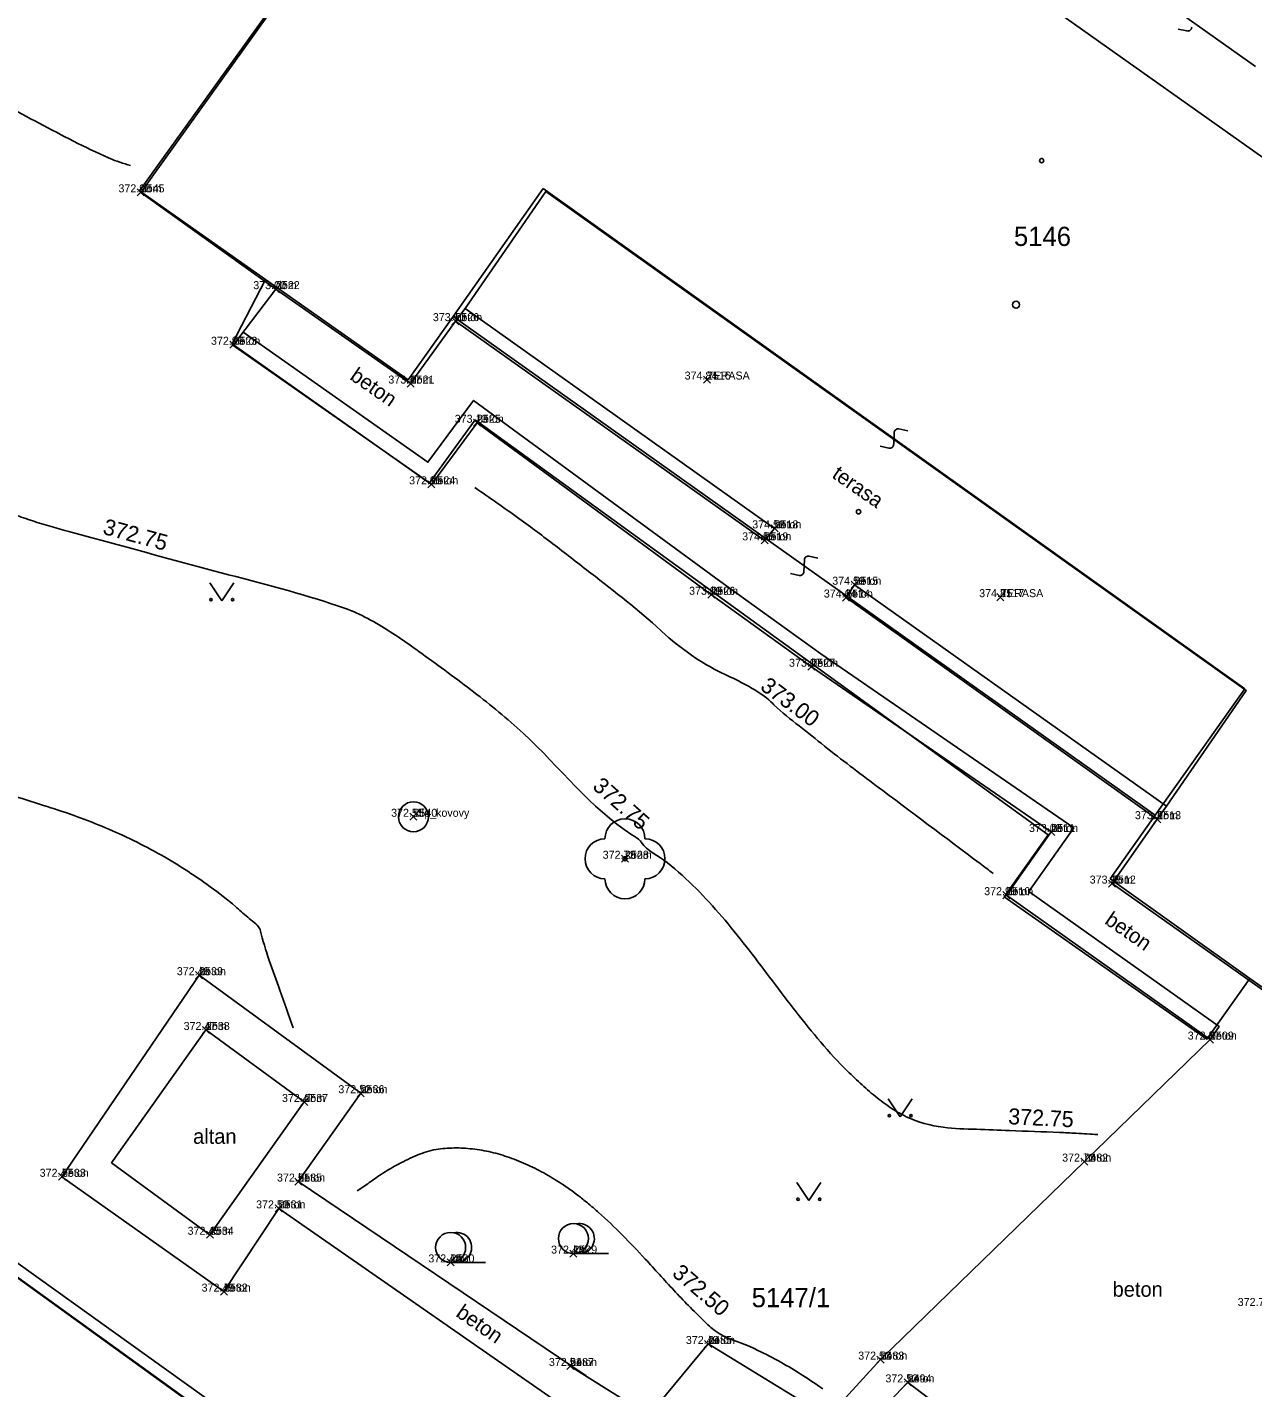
# Model space of a CAD drawing. Extents: x -400488 to -400124, y -1251493 to -1251223.
# Drawn here: x -400354.88 to -400324.23, y -1251353.83 to -1251319.82 of the extents above; entities that cross this region are included whole.
import ezdxf

# ---------------------------------------------------------------- set-up
doc = ezdxf.new("R2010")
doc.units = 0
for name, color, linetype in [('Level 20', 7, 'Continuous'), ('Level 21', 7, 'Continuous'), ('Level 22', 7, 'Continuous'), ('Level 23', 7, 'Continuous'), ('Level 31', 7, 'Continuous'), ('Level 32', 7, 'Continuous'), ('Level 34', 7, 'Continuous'), ('Level 35', 7, 'Continuous'), ('Level 36', 7, 'Continuous'), ('Level 49', 7, 'Continuous'), ('Level 60', 7, 'Continuous'), ('Level 63', 7, 'Continuous')]:
    doc.layers.add(name, color=color, linetype=linetype)

msp = doc.modelspace()

# ---------------------------------------------------------------- linework, layer by layer
at = {"layer": 'Level 20'}
for p, q in [((-400352.128, -1251324.038), (-400351.952, -1251323.862)), ((-400351.952, -1251324.038), (-400352.128, -1251323.862)), ((-400348.748, -1251326.458), (-400348.572, -1251326.282)), ((-400348.572, -1251326.458), (-400348.748, -1251326.282)), ((-400344.258, -1251327.258), (-400344.082, -1251327.082)), ((-400344.082, -1251327.258), (-400344.258, -1251327.082)), ((-400349.808, -1251327.848), (-400349.632, -1251327.672)), ((-400349.632, -1251327.848), (-400349.808, -1251327.672)), ((-400345.378, -1251328.818), (-400345.202, -1251328.642)), ((-400345.202, -1251328.818), (-400345.378, -1251328.642)), ((-400337.968, -1251328.718), (-400337.792, -1251328.542)), ((-400337.792, -1251328.718), (-400337.968, -1251328.542)), ((-400343.718, -1251329.798), (-400343.542, -1251329.622)), ((-400343.542, -1251329.798), (-400343.718, -1251329.622)), ((-400344.858, -1251331.338), (-400344.682, -1251331.162)), ((-400344.682, -1251331.338), (-400344.858, -1251331.162)), ((-400336.278, -1251332.438), (-400336.102, -1251332.262)), ((-400336.102, -1251332.438), (-400336.278, -1251332.262)), ((-400336.528, -1251332.738), (-400336.352, -1251332.562)), ((-400336.352, -1251332.738), (-400336.528, -1251332.562)), ((-400334.278, -1251333.848), (-400334.102, -1251333.672)), ((-400334.102, -1251333.848), (-400334.278, -1251333.672)), ((-400337.858, -1251334.098), (-400337.682, -1251333.922)), ((-400337.682, -1251334.098), (-400337.858, -1251333.922)), ((-400334.488, -1251334.168), (-400334.312, -1251333.992)), ((-400334.312, -1251334.168), (-400334.488, -1251333.992)), ((-400330.628, -1251334.158), (-400330.452, -1251333.982)), ((-400330.452, -1251334.158), (-400330.628, -1251333.982)), ((-400335.358, -1251335.898), (-400335.182, -1251335.722)), ((-400335.182, -1251335.898), (-400335.358, -1251335.722)), ((-400345.308, -1251339.648), (-400345.132, -1251339.472)), ((-400345.132, -1251339.648), (-400345.308, -1251339.472)), ((-400326.708, -1251339.708), (-400326.532, -1251339.532)), ((-400326.532, -1251339.708), (-400326.708, -1251339.532)), ((-400329.358, -1251340.028), (-400329.182, -1251339.852)), ((-400329.182, -1251340.028), (-400329.358, -1251339.852)), ((-400340.018, -1251340.698), (-400339.842, -1251340.522)), ((-400339.842, -1251340.698), (-400340.018, -1251340.522)), ((-400327.838, -1251341.318), (-400327.662, -1251341.142)), ((-400327.662, -1251341.318), (-400327.838, -1251341.142)), ((-400330.478, -1251341.608), (-400330.302, -1251341.432)), ((-400330.302, -1251341.608), (-400330.478, -1251341.432)), ((-400350.668, -1251343.608), (-400350.492, -1251343.432)), ((-400350.492, -1251343.608), (-400350.668, -1251343.432)), ((-400350.498, -1251344.978), (-400350.322, -1251344.802)), ((-400350.322, -1251344.978), (-400350.498, -1251344.802)), ((-400325.388, -1251345.218), (-400325.212, -1251345.042)), ((-400325.212, -1251345.218), (-400325.388, -1251345.042)), ((-400348.038, -1251346.778), (-400347.862, -1251346.602)), ((-400347.862, -1251346.778), (-400348.038, -1251346.602)), ((-400346.628, -1251346.558), (-400346.452, -1251346.382)), ((-400346.452, -1251346.558), (-400346.628, -1251346.382)), ((-400328.528, -1251348.268), (-400328.352, -1251348.092)), ((-400328.352, -1251348.268), (-400328.528, -1251348.092)), ((-400354.098, -1251348.648), (-400353.922, -1251348.472)), ((-400353.922, -1251348.648), (-400354.098, -1251348.472)), ((-400348.188, -1251348.768), (-400348.012, -1251348.592)), ((-400348.012, -1251348.768), (-400348.188, -1251348.592)), ((-400348.678, -1251349.438), (-400348.502, -1251349.262)), ((-400348.502, -1251349.438), (-400348.678, -1251349.262)), ((-400350.398, -1251350.098), (-400350.222, -1251349.922)), ((-400350.222, -1251350.098), (-400350.398, -1251349.922)), ((-400341.308, -1251350.568), (-400341.132, -1251350.392)), ((-400341.132, -1251350.568), (-400341.308, -1251350.392)), ((-400344.378, -1251350.788), (-400344.202, -1251350.612)), ((-400344.202, -1251350.788), (-400344.378, -1251350.612)), ((-400350.048, -1251351.518), (-400349.872, -1251351.342)), ((-400349.872, -1251351.518), (-400350.048, -1251351.342)), ((-400337.938, -1251352.828), (-400337.762, -1251352.652)), ((-400337.762, -1251352.828), (-400337.938, -1251352.652)), ((-400333.628, -1251353.218), (-400333.452, -1251353.042)), ((-400333.452, -1251353.218), (-400333.628, -1251353.042)), ((-400341.388, -1251353.378), (-400341.212, -1251353.202)), ((-400341.212, -1251353.378), (-400341.388, -1251353.202)), ((-400332.948, -1251353.788), (-400332.772, -1251353.612)), ((-400332.772, -1251353.788), (-400332.948, -1251353.612))]:
    msp.add_line(p, q, dxfattribs=at)
at = {"layer": 'Level 31'}
msp.add_line((-400326.388, -1251339.294), (-400334.19, -1251333.76), dxfattribs=at)
for points in [[(-400348.66, -1251326.37), (-400349.72, -1251327.76), (-400344.77, -1251331.25), (-400343.63, -1251329.71), (-400337.77, -1251334.01), (-400335.27, -1251335.81)], [(-400343.93, -1251326.85), (-400336.19, -1251332.35), (-400336.44, -1251332.65), (-400344.17, -1251327.17)], [(-400349.477, -1251327.442), (-400344.859, -1251330.698), (-400343.715, -1251329.152), (-400337.535, -1251333.686), (-400335.036, -1251335.485)], [(-400326.62, -1251339.62), (-400334.4, -1251334.08), (-400334.19, -1251333.76)], [(-400325.3, -1251345.13), (-400325.069, -1251344.804), (-400329.832, -1251341.425), (-400328.709, -1251339.84), (-400335.036, -1251335.485)], [(-400325.3, -1251345.13), (-400330.39, -1251341.52), (-400329.27, -1251339.94), (-400335.27, -1251335.81)], [(-400340.901, -1251353.538), (-400348.1, -1251348.68), (-400346.54, -1251346.47), (-400350.58, -1251343.52), (-400354.01, -1251348.56)], [(-400325.3, -1251345.13), (-400328.44, -1251348.18), (-400333.54, -1251353.13), (-400334.86, -1251354.57), (-400337.85, -1251352.74), (-400339.33, -1251354.53), (-400341.3, -1251353.29)], [(-400341.64, -1251354.18), (-400348.59, -1251349.35), (-400349.96, -1251351.43), (-400354.01, -1251348.56)], [(-400340.16, -1251356.34), (-400340.828, -1251357.382), (-400337.51, -1251359.51), (-400334.26, -1251355.13), (-400332.86, -1251353.7), (-400328.72, -1251356.82), (-400328.3, -1251357.14), (-400327.46, -1251357.74), (-400326.93, -1251358.11), (-400329.7, -1251364.82)]]:
    msp.add_lwpolyline(points, dxfattribs=at)
at = {"layer": 'Level 34'}
for points in [[(-400318.045, -1251327.281), (-400335.362, -1251315.009), (-400331.92, -1251310.33)], [(-400348.66, -1251326.37), (-400352.04, -1251323.95), (-400347.15, -1251317.14), (-400345.723, -1251318.156), (-400342.07, -1251313.16), (-400343.58, -1251312.05)], [(-400326.62, -1251339.62), (-400326.388, -1251339.294), (-400324.4, -1251336.403), (-400341.911, -1251323.928), (-400343.93, -1251326.85), (-400344.17, -1251327.17), (-400345.29, -1251328.73), (-400348.66, -1251326.37)], [(-400312.65, -1251334.13), (-400314.209, -1251333.021), (-400317.753, -1251338.016), (-400316.22, -1251339.14), (-400321.09, -1251345.94), (-400327.75, -1251341.23)], [(-400327.75, -1251341.23), (-400326.62, -1251339.62)], [(-400350.41, -1251344.89), (-400352.77, -1251348.21), (-400350.31, -1251350.01), (-400347.95, -1251346.69), (-400350.41, -1251344.89)]]:
    msp.add_lwpolyline(points, dxfattribs=at)
msp.add_circle((-400330.151, -1251326.758), 0.0875, dxfattribs=at)
at = {"layer": 'Level 35'}
for points in [[(-400336.543, -1251364.474), (-400341.42, -1251360.95), (-400349.22, -1251355.33), (-400374.14, -1251337.36)], [(-400333.65, -1251366.42), (-400333.57, -1251366.16), (-400344.8, -1251358.11), (-400358.88, -1251348.03)]]:
    msp.add_lwpolyline(points, dxfattribs=at)
at = {"layer": 'Level 36'}
for p, q in [((-400350.014, -1251334.161), (-400350.314, -1251333.711)), ((-400350.014, -1251334.161), (-400349.714, -1251333.711)), ((-400333.048, -1251347.064), (-400333.348, -1251346.614)), ((-400333.048, -1251347.064), (-400332.748, -1251346.614)), ((-400344.29, -1251350.7), (-400343.415, -1251350.7)), ((-400341.22, -1251350.48), (-400340.345, -1251350.48))]:
    msp.add_line(p, q, dxfattribs=at)
for centre, radius in [((-400350.284, -1251334.131), 0.03), ((-400349.744, -1251334.131), 0.03), ((-400339.93, -1251340.61), 0.05), ((-400333.318, -1251347.034), 0.03), ((-400332.778, -1251347.034), 0.03), ((-400341.22, -1251350.105), 0.375), ((-400344.29, -1251350.325), 0.375)]:
    msp.add_circle(centre, radius, dxfattribs=at)
for centre, radius, start, end in [((-400339.93, -1251340.11), 0.5, 0, 180), ((-400340.43, -1251340.61), 0.5, 90, 270), ((-400339.43, -1251340.61), 0.5, 270, 90), ((-400339.93, -1251341.11), 0.5, 180, 0), ((-400341.07, -1251350.105), 0.375, 270, 101.537), ((-400344.14, -1251350.325), 0.375, 270, 101.537)]:
    msp.add_arc(centre, radius, start, end, dxfattribs=at)
at = {"layer": 'Level 49'}
for points in [[(-400352.293, -1251323.278), (-400352.826, -1251323.097), (-400352.844, -1251323.089), (-400354.58, -1251322.223), (-400356.287, -1251321.302), (-400358.007, -1251320.393), (-400358.886, -1251319.963), (-400359.784, -1251319.561), (-400359.802, -1251319.557), (-400360.521, -1251319.456), (-400361.243, -1251319.387), (-400361.966, -1251319.353), (-400362.686, -1251319.354), (-400362.706, -1251319.359), (-400363.04, -1251319.588), (-400363.343, -1251319.84), (-400363.891, -1251320.382), (-400364.419, -1251320.929), (-400364.995, -1251321.421), (-400366.014, -1251322.099), (-400366.527, -1251322.437), (-400367.024, -1251322.796), (-400367.495, -1251323.197), (-400367.955, -1251323.654), (-400368.388, -1251324.135), (-400368.82, -1251324.624), (-400370.184, -1251324.602), (-400371.084, -1251324.11), (-400371.985, -1251323.601), (-400372.84, -1251323.028), (-400374.376, -1251321.785), (-400375.093, -1251321.106), (-400376.539, -1251320.249), (-400376.957, -1251320.548), (-400377.775, -1251321.215), (-400378.615, -1251321.804), (-400379.061, -1251322.005), (-400379.52, -1251322.108)], [(-400328.103, -1251347.503), (-400328.651, -1251347.472), (-400329.066, -1251347.452), (-400330.312, -1251347.405), (-400331.142, -1251347.372), (-400331.972, -1251347.323), (-400332.896, -1251347.057), (-400333.323, -1251346.808), (-400333.723, -1251346.506), (-400334.094, -1251346.175), (-400334.453, -1251345.833), (-400335.115, -1251345.1), (-400336.315, -1251343.568), (-400337.506, -1251342.056), (-400338.154, -1251341.354), (-400338.869, -1251340.711), (-400338.874, -1251340.707), (-400339.524, -1251340.192), (-400339.544, -1251340.164), (-400339.547, -1251340.161), (-400339.758, -1251340.008), (-400342.468, -1251337.479), (-400342.48, -1251337.468), (-400343.713, -1251336.442), (-400344.355, -1251335.958), (-400345.008, -1251335.482), (-400346.081, -1251334.763), (-400346.65, -1251334.464), (-400347.249, -1251334.241), (-400350.219, -1251333.411), (-400353.193, -1251332.601), (-400353.935, -1251332.4), (-400354.856, -1251332.126), (-400355.313, -1251331.975), (-400355.768, -1251331.816), (-400355.789, -1251331.804), (-400356.24, -1251331.418), (-400356.681, -1251331.026), (-400357.542, -1251330.226), (-400359.22, -1251328.579), (-400360.038, -1251327.712), (-400360.053, -1251327.685), (-400360.059, -1251327.678)], [(-400330.72, -1251340.978), (-400331.048, -1251340.732), (-400333.648, -1251338.783), (-400334.938, -1251337.795), (-400335.573, -1251337.287), (-400336.2, -1251336.768), (-400336.205, -1251336.763), (-400336.228, -1251336.739), (-400336.699, -1251336.382), (-400337.225, -1251336.099), (-400337.764, -1251335.831), (-400338.27, -1251335.517), (-400339.01, -1251334.926), (-400339.037, -1251334.901), (-400340.783, -1251333.471), (-400341.676, -1251332.78), (-400342.581, -1251332.104), (-400343.686, -1251331.33)], [(-400348.228, -1251344.84), (-400348.565, -1251343.891), (-400349.051, -1251342.39), (-400349.06, -1251342.362), (-400349.066, -1251342.352), (-400349.366, -1251342.071), (-400349.672, -1251341.804), (-400350.301, -1251341.309), (-400351.62, -1251340.467), (-400353.013, -1251339.798), (-400353.734, -1251339.52), (-400354.47, -1251339.274), (-400357.344, -1251338.386), (-400358.925, -1251337.893), (-400359.259, -1251337.827), (-400359.747, -1251337.833), (-400359.988, -1251337.891), (-400360.104, -1251337.935), (-400360.161, -1251337.96), (-400360.216, -1251337.989), (-400360.272, -1251338.047), (-400360.248, -1251338.108), (-400360.036, -1251338.239), (-400359.823, -1251338.337)], [(-400334.986, -1251353.857), (-400335.08, -1251353.793), (-400335.621, -1251353.439), (-400336.177, -1251353.117), (-400336.753, -1251352.83), (-400336.828, -1251352.796), (-400337.672, -1251352.414), (-400337.958, -1251352.157), (-400338.343, -1251351.78), (-400338.709, -1251351.396), (-400339.424, -1251350.616), (-400340.592, -1251349.451), (-400340.813, -1251349.261), (-400341.045, -1251349.073), (-400341.469, -1251348.764), (-400341.908, -1251348.493), (-400342.354, -1251348.267), (-400342.583, -1251348.168), (-400342.819, -1251348.079), (-400343.277, -1251347.944), (-400343.745, -1251347.863), (-400344.204, -1251347.84), (-400344.431, -1251347.851), (-400344.655, -1251347.878), (-400345.127, -1251348.02), (-400345.595, -1251348.243), (-400345.973, -1251348.463), (-400346.327, -1251348.706), (-400346.625, -1251348.915)]]:
    msp.add_spline(points, degree=3, dxfattribs=at)
at = {"layer": 'Level 60'}
msp.add_circle((-400345.22, -1251339.56), 0.375, dxfattribs=at)
at = {"layer": 'Level 63'}
for p, q in [((-400347.18, -1251317.12), (-400352.07, -1251323.91)), ((-400352.07, -1251323.91), (-400347.18, -1251317.12)), ((-400327.34, -1251318.55), (-400324.16, -1251320.8)), ((-400326.095, -1251319.868), (-400325.877, -1251319.916)), ((-400344.23, -1251327.05), (-400341.98, -1251323.85)), ((-400341.98, -1251323.85), (-400324.43, -1251336.36)), ((-400352.07, -1251323.91), (-400348.92, -1251326.13)), ((-400348.92, -1251326.13), (-400352.07, -1251323.91)), ((-400348.92, -1251326.13), (-400349.76, -1251327.75)), ((-400349.76, -1251327.75), (-400348.92, -1251326.13)), ((-400348.92, -1251326.13), (-400345.35, -1251328.64)), ((-400345.35, -1251328.64), (-400344.23, -1251327.05)), ((-400326.67, -1251339.52), (-400344.23, -1251327.05)), ((-400349.76, -1251327.75), (-400344.82, -1251331.21)), ((-400344.82, -1251331.21), (-400349.76, -1251327.75)), ((-400344.82, -1251331.21), (-400343.68, -1251329.64)), ((-400343.68, -1251329.64), (-400344.82, -1251331.21)), ((-400343.68, -1251329.64), (-400329.35, -1251340.01)), ((-400329.35, -1251340.01), (-400343.68, -1251329.64)), ((-400333.211, -1251330.252), (-400333.199, -1251329.958)), ((-400333.078, -1251329.864), (-400332.86, -1251329.912)), ((-400333.55, -1251330.298), (-400333.332, -1251330.346)), ((-400335.323, -1251333.044), (-400335.105, -1251333.092)), ((-400335.456, -1251333.432), (-400335.444, -1251333.138)), ((-400335.795, -1251333.478), (-400335.577, -1251333.526)), ((-400324.43, -1251336.36), (-400326.67, -1251339.52)), ((-400327.8, -1251341.11), (-400326.67, -1251339.52)), ((-400329.35, -1251340.01), (-400330.45, -1251341.56)), ((-400330.45, -1251341.56), (-400329.35, -1251340.01)), ((-400324.3, -1251343.6), (-400327.8, -1251341.11)), ((-400330.45, -1251341.56), (-400325.38, -1251345.12)), ((-400325.38, -1251345.12), (-400330.45, -1251341.56)), ((-400325.38, -1251345.12), (-400324.3, -1251343.6)), ((-400324.3, -1251343.6), (-400325.38, -1251345.12)), ((-400324.3, -1251343.6), (-400321.16, -1251345.83)), ((-400321.16, -1251345.83), (-400324.3, -1251343.6)), ((-400336.35, -1251364.63), (-400362.18, -1251345.99)), ((-400362.18, -1251345.99), (-400336.35, -1251364.63)), ((-400335.63, -1251348.7), (-400335.33, -1251349.15)), ((-400335.33, -1251349.15), (-400335.03, -1251348.7))]:
    msp.add_line(p, q, dxfattribs=at)
for centre, radius in [((-400329.51, -1251323.156), 0.054), ((-400334.09, -1251331.936), 0.054), ((-400335.6, -1251349.12), 0.03), ((-400335.06, -1251349.12), 0.03)]:
    msp.add_circle(centre, radius, dxfattribs=at)
for centre, start, end in [((-400325.856, -1251319.818), 257.753, 357.7631), ((-400333.099, -1251329.962), 77.7527, 177.7631), ((-400333.311, -1251330.248), 257.753, 357.7631), ((-400335.344, -1251333.142), 77.7527, 177.7631), ((-400335.556, -1251333.428), 257.753, 357.7631)]:
    msp.add_arc(centre, 0.1, start, end, dxfattribs=at)

# ---------------------------------------------------------------- texts
at = {"layer": 'Level 21'}
for s, p in [('2545', (-400352.04, -1251323.95)), ('2522', (-400348.66, -1251326.37)), ('2520', (-400344.17, -1251327.17)), ('2523', (-400349.72, -1251327.76)), ('2521', (-400345.29, -1251328.73)), ('2516', (-400337.88, -1251328.63)), ('2525', (-400343.63, -1251329.71)), ('2524', (-400344.77, -1251331.25)), ('2518', (-400336.19, -1251332.35)), ('2519', (-400336.44, -1251332.65)), ('2515', (-400334.19, -1251333.76)), ('2526', (-400337.77, -1251334.01)), ('2514', (-400334.4, -1251334.08)), ('2517', (-400330.54, -1251334.07)), ('2527', (-400335.27, -1251335.81)), ('2540', (-400345.22, -1251339.56)), ('2513', (-400326.62, -1251339.62)), ('2511', (-400329.27, -1251339.94)), ('2528', (-400339.93, -1251340.61)), ('2512', (-400327.75, -1251341.23)), ('2510', (-400330.39, -1251341.52)), ('2539', (-400350.58, -1251343.52)), ('2538', (-400350.41, -1251344.89)), ('2509', (-400325.3, -1251345.13)), ('2536', (-400346.54, -1251346.47)), ('2537', (-400347.95, -1251346.69)), ('2482', (-400328.44, -1251348.18)), ('2533', (-400354.01, -1251348.56)), ('2535', (-400348.1, -1251348.68)), ('2531', (-400348.59, -1251349.35)), ('2534', (-400350.31, -1251350.01)), ('2529', (-400341.22, -1251350.48)), ('2530', (-400344.29, -1251350.7)), ('2532', (-400349.96, -1251351.43)), ('2485', (-400337.85, -1251352.74)), ('2487', (-400341.3, -1251353.29)), ('2483', (-400333.54, -1251353.13)), ('2494', (-400332.86, -1251353.7))]:
    msp.add_text(s, height=0.2, dxfattribs=at).set_placement(p)
at = {"layer": 'Level 22'}
for s, p in [('dom', (-400352.04, -1251323.95)), ('dom', (-400348.66, -1251326.37)), ('beton', (-400344.17, -1251327.17)), ('beton', (-400349.72, -1251327.76)), ('dom', (-400345.29, -1251328.73)), ('TERASA', (-400337.88, -1251328.63)), ('beton', (-400343.63, -1251329.71)), ('beton', (-400344.77, -1251331.25)), ('beton', (-400336.19, -1251332.35)), ('beton', (-400336.44, -1251332.65)), ('beton', (-400334.19, -1251333.76)), ('beton', (-400337.77, -1251334.01)), ('beton', (-400334.4, -1251334.08)), ('TERASA', (-400330.54, -1251334.07)), ('beton', (-400335.27, -1251335.81)), ('stlp_kovovy', (-400345.22, -1251339.56)), ('dom', (-400326.62, -1251339.62)), ('beton', (-400329.27, -1251339.94)), ('strom', (-400339.93, -1251340.61)), ('dom', (-400327.75, -1251341.23)), ('beton', (-400330.39, -1251341.52)), ('beton', (-400350.58, -1251343.52)), ('dom', (-400350.41, -1251344.89)), ('beton', (-400325.3, -1251345.13)), ('beton', (-400346.54, -1251346.47)), ('dom', (-400347.95, -1251346.69)), ('beton', (-400328.44, -1251348.18)), ('beton', (-400354.01, -1251348.56)), ('beton', (-400348.1, -1251348.68)), ('beton', (-400348.59, -1251349.35)), ('dom', (-400350.31, -1251350.01)), ('krik', (-400341.22, -1251350.48)), ('krik', (-400344.29, -1251350.7)), ('beton', (-400349.96, -1251351.43)), ('beton', (-400337.85, -1251352.74)), ('beton', (-400341.3, -1251353.29)), ('beton', (-400333.54, -1251353.13)), ('beton', (-400332.86, -1251353.7))]:
    msp.add_text(s, height=0.2, dxfattribs=at).set_placement(p)
at = {"layer": 'Level 23'}
for s, p in [('372.98', (-400352.598, -1251323.95)), ('373.00', (-400349.226, -1251326.37)), ('373.50', (-400344.736, -1251327.17)), ('372.96', (-400350.283, -1251327.76)), ('373.47', (-400345.848, -1251328.73)), ('374.84', (-400338.438, -1251328.63)), ('373.13', (-400344.188, -1251329.71)), ('372.95', (-400345.329, -1251331.25)), ('374.58', (-400336.748, -1251332.35)), ('374.55', (-400336.999, -1251332.65)), ('374.59', (-400334.748, -1251333.76)), ('373.09', (-400338.328, -1251334.01)), ('374.64', (-400334.958, -1251334.08)), ('374.81', (-400331.073, -1251334.07)), ('373.07', (-400335.828, -1251335.81)), ('372.55', (-400345.779, -1251339.56)), ('373.37', (-400327.178, -1251339.62)), ('373.08', (-400329.828, -1251339.94)), ('372.72', (-400340.488, -1251340.61)), ('373.35', (-400328.309, -1251341.23)), ('372.99', (-400330.948, -1251341.52)), ('372.48', (-400351.138, -1251343.52)), ('372.47', (-400350.968, -1251344.89)), ('372.87', (-400325.858, -1251345.13)), ('372.52', (-400347.098, -1251346.47)), ('372.47', (-400348.508, -1251346.69)), ('372.72', (-400328.998, -1251348.18)), ('372.47', (-400354.568, -1251348.56)), ('372.51', (-400348.633, -1251348.68)), ('372.50', (-400349.156, -1251349.35)), ('372.45', (-400350.869, -1251350.01)), ('372.43', (-400341.778, -1251350.48)), ('372.48', (-400344.848, -1251350.7)), ('372.49', (-400350.518, -1251351.43)), ('372.73', (-400324.608, -1251351.79)), ('372.49', (-400338.408, -1251352.74)), ('372.51', (-400341.833, -1251353.29)), ('372.53', (-400334.098, -1251353.13)), ('372.52', (-400333.418, -1251353.7))]:
    msp.add_text(s, height=0.2, dxfattribs=at).set_placement(p)
at = {"layer": 'Level 31'}
for s, p in [('beton', (-400346.834, -1251328.61)), ('terasa', (-400334.779, -1251331.065)), ('beton', (-400327.959, -1251342.214)), ('beton', (-400344.183, -1251352.031))]:
    msp.add_text(s, height=0.375, rotation=325.2178, dxfattribs=at).set_placement(p)
msp.add_text('beton', height=0.375, dxfattribs=at).set_placement((-400327.736, -1251351.559))
at = {"layer": 'Level 32'}
msp.add_text('altan', height=0.375, dxfattribs=at).set_placement((-400350.731, -1251347.736))
at = {"layer": 'Level 49'}
for s, rotation, p in [('372.75', 344.7447, (-400353.01, -1251332.485)), ('373.00', 323.4023, (-400336.573, -1251336.36)), ('372.75', 318.4551, (-400340.766, -1251338.836)), ('372.75', 357.1725, (-400330.353, -1251347.244)), ('372.50', 319.3872, (-400338.776, -1251351.011))]:
    msp.add_text(s, height=0.4, rotation=rotation, dxfattribs=at).set_placement(p)
at = {"layer": 'Level 63'}
for s, p in [('5146', (-400330.204, -1251325.29)), ('5147/1', (-400336.762, -1251351.82))]:
    msp.add_text(s, height=0.48, dxfattribs=at).set_placement(p)

doc.saveas('drawing.dxf')
